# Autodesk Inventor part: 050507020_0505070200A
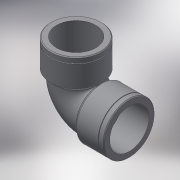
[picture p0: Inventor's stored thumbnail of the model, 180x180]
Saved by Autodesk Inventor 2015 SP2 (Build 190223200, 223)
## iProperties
Created: 2017-05
Part Number: 050507020_0505070200A
Material: Generic
Description: PLASSON THREADED ELBOW 2"-2"
Document SubType Name: Modeling
Designer: KIM
Density: 1 g/cm^3
Appearance: Default
Author: KIM
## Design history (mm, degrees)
derived "050507.ipt"
feature "Solid1::050507.ipt"
tag "TaggingFeature1"
body "Solid1"
other parameters: "d0" = 65, "d2" = 0.5, "d3" = 0.5, "d4" = 73.6528, "d5" = 56.656, "d7" = 135 deg, "d8" = 36, "d9" = 6, "d19" = 1.13312, "d30" = 50.9904, "d31" = 62.3216, "d33" = 90 deg, "d35" = 90 deg, "d36" = 90 deg, "d37" = 2.8328, "Rp_" = 56.656, "A_" = 65
